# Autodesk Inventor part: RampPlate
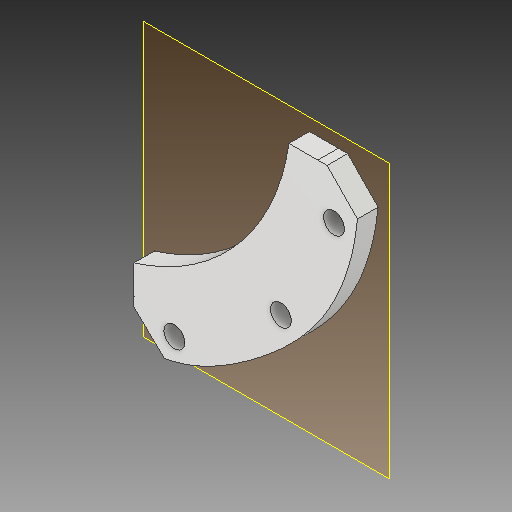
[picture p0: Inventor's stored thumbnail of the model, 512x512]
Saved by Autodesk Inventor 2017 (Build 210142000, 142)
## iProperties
Created: 2017-04
Part Number: RampPlate
Material: ABS Plastic
Document SubType Name: Modeling
Designer: 1460374
Density: 1.06 g/cm^3
Appearance: Smooth - White
Author: 1460374
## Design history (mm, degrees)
workplane "Work Plane1"
sketch "Sketch1"
  geometry: L1 (-38.276, -23.327)-(-38.276, -16.977); L2 (18.414, 41.452)-(12.064, 41.452); L3 (21.272, 41.452)-(30.642, 31.846) reference; L4 (21.272, 41.452)-(18.414, 41.452) reference; L5 (-38.276, -23.327)-(-38.276, -26.185) reference; L6 (-28.844, -35.157)-(-38.276, -26.185) reference; C1 r 3.225 at (7.037, -5.574) reference; C2 r 3.225 at (-25.835, -27.792) reference; C3 r 3.225 at (23.412, 27.176) reference; A1 r 71.128 centre (-58.386, 51.249) between (-38.276, -16.977) and (12.064, 41.452); 1 further point
  constraints: 4 end point, 2 point on circle, 1 centre point, 1 horizontal, 1 vertical
  dimensions: "d0" = 6.35 distance of L1.start L1.end; "d1" = 6.35 distance of L2.start L2.end
extrude "Extrusion1" new body sketch "Sketch1" distance "d2" = 6.35; taper "d3" = 0 deg
thicken "Thicken1" dims "d4" = 2.54, "d5" = 2.54
body "Solid1"
node "Reference2"
